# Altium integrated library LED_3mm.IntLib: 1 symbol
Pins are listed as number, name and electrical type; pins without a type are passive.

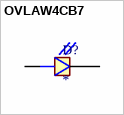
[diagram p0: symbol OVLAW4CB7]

## OVLAW4CB7
designator D?
Ovlaw4Cb7 White LED 3mm (T-1) Round Lens Through Hole Package ¦ Optek (TT Electronics) OVLAW4CB7; MF: TT Electronics/Optek
footprint LEDRD254W50D305H520P
pins: A, C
